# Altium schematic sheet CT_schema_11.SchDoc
size 391 x 238 mm
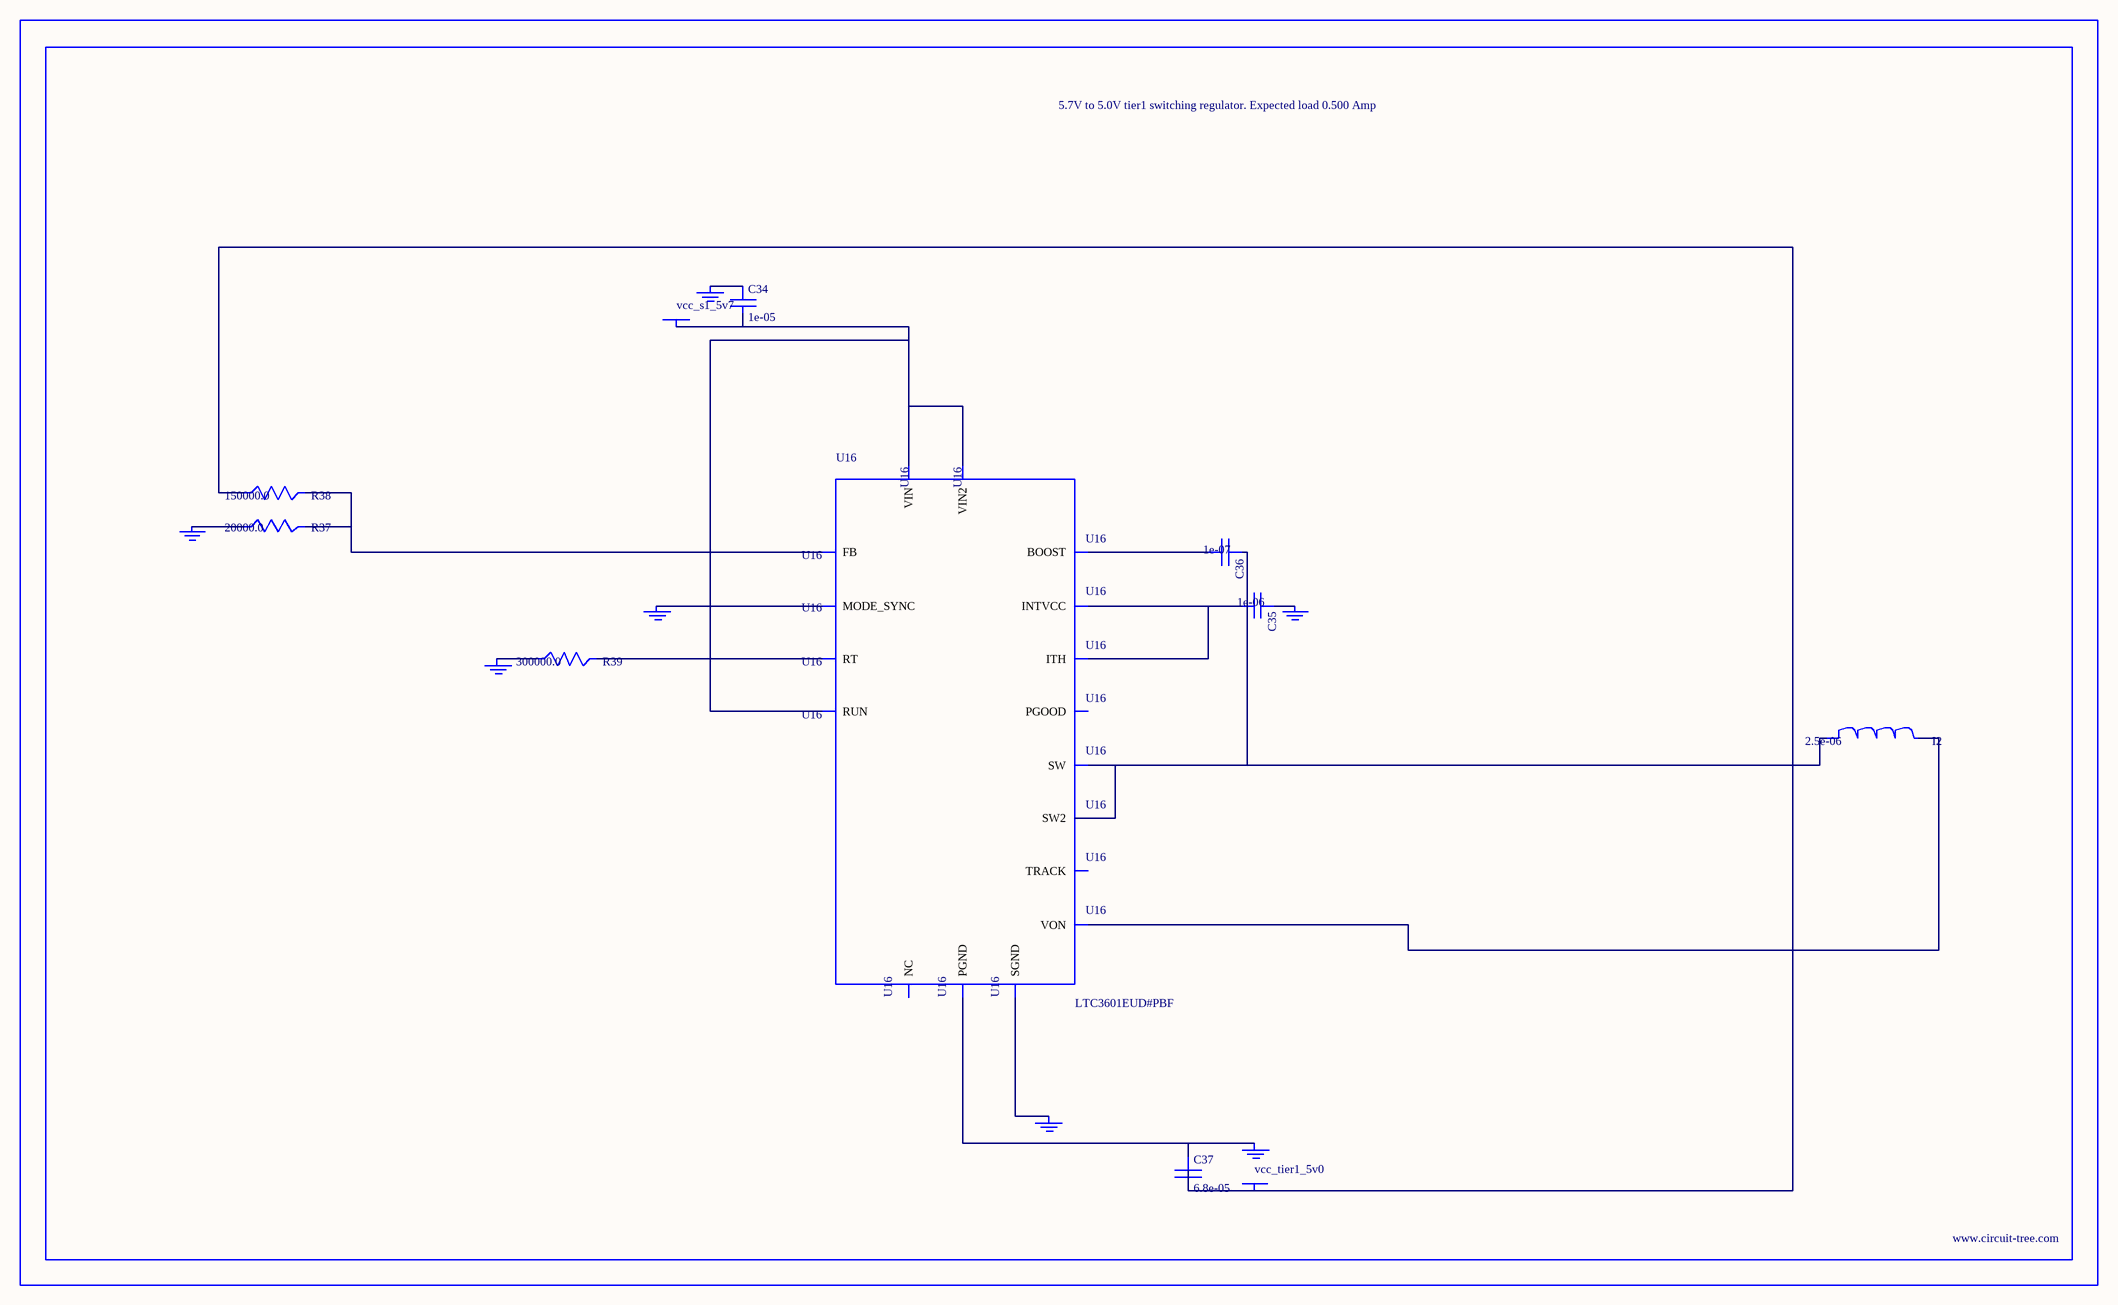
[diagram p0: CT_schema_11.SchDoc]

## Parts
BORDER10  (no value)
C34  1e-05  [C0805]
C35  1e-06  [C0603]
C36  1e-07  [C0402]
C37  6.8e-05  [2220]
GND_INSTANCE_10_0  (no value)
GND_INSTANCE_10_1  (no value)
GND_INSTANCE_10_2  (no value)
GND_INSTANCE_10_3  (no value)
GND_INSTANCE_10_4  (no value)
GND_INSTANCE_10_5  (no value)
GND_INSTANCE_10_6  (no value)
I2  2.5e-06  [DR1040]
POWER_INSTANCE_10_0  vcc_s1_5v7
POWER_INSTANCE_10_1  vcc_tier1_5v0
R37  20000.0  [R0603]
R38  150000.0  [R0603]
R39  300000.0  [R0603]
U16  LTC3601EUD#PBF  [QFN-16_EP]

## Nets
NetC34_1: C34.1 GND_INSTANCE_10_5.0(GND)
NetC34_2: C34.2 POWER_INSTANCE_10_0.0(PWR) U16.14(RUN) U16.15(VIN) U16.16(VIN2)
NetC35_1: C35.1 GND_INSTANCE_10_1.0(GND)
NetC35_2: C35.2 U16.7(INTVCC) U16.12(ITH)
NetC36_1: C36.1 I2.1 U16.3(SW) U16.4(SW2)
NetC36_2: C36.2 U16.6(BOOST)
NetC37_1: C37.1 GND_INSTANCE_10_6.0(GND) U16.17(PGND)
NetC37_2: C37.2 I2.2 POWER_INSTANCE_10_1.0(PWR) R38.1 U16.8(VON)
NetGND_INSTANCE_10_0_0: GND_INSTANCE_10_0.0(GND) U16.1(MODE_SYNC)
NetGND_INSTANCE_10_2_0: GND_INSTANCE_10_2.0(GND) U16.9(SGND)
NetGND_INSTANCE_10_3_0: GND_INSTANCE_10_3.0(GND) R39.1
NetGND_INSTANCE_10_4_0: GND_INSTANCE_10_4.0(GND) R37.1
NetR37_2: R37.2 R38.2 U16.11(FB)
NetR39_2: R39.2 U16.10(RT)

Not connected (* = marked no-connect by the designer): U16 2(PGOOD) 5(NC) 13(TRACK)

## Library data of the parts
BORDER10 = BORDER_PAGE10
C34 = C0805C106K8RACTU
C35 = C0603C105K3RACTU
C36 = C0402C104K3RACTU
C37 = C5750X5R1A686M
GND_INSTANCE_10_0-GND_INSTANCE_10_6 = GND
I2 = DR1040-2R5-R
POWER_INSTANCE_10_0 POWER_INSTANCE_10_1 = PWR
R37 = RC0603JR-0720KL
R38 = RC0603JR-07150KL
R39 = RC0603JR-07300KL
